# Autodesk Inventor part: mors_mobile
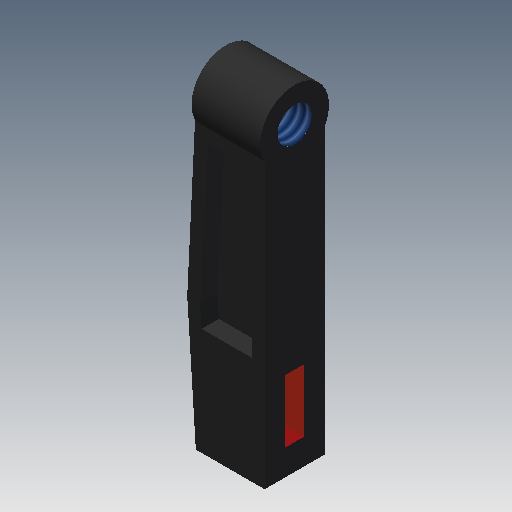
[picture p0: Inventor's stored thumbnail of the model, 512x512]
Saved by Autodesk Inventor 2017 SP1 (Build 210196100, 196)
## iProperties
Shininess: 64.0
Length Units: 11269
Angle Units: 11279
Time Units: 11290
Mass Units: 11283
Length Display Precision: 3
Angle Display Precision: 2
Compacted: True
Part Number: mors_mobile
Document SubType Name: Modeling
Created: 2003-07
Material: Générique
Designer: trameau
Density: 1 g/cm^3
Appearance: Caoutchouc (Noir)
Density: 0.0
Volumn: 0.0
Area: 0.0
PropertySet Name: Model Information
Control State: 0
Master: False
Checked Out: False
Author: trameau
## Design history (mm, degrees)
sketch "Esquisse1"
  geometry: L1 (17.214, 43.337)-(17.214, -26.663); L2 (17.214, -26.663)-(1.214, -26.663); L3 (1.214, -26.663)-(-0.786, 3.337); L4 (-0.786, 3.337)-(1.214, 43.337); L5 (1.214, 43.337)-(17.214, 43.337)
  constraints: 10 end point, 1 parallel, 1 perpendicular, 1 vertical
  dimensions: "d0" = 70 distance of L1.start L1.end; "d1" = 16 distance of L1.end L2.end; "d2" = 18 distance from line of L1 L3.end; "d3" = 16 distance of L4.end L1.start (= d1); "d4" = 30 distance from line of L2 L3.end
extrude "Extrusion1" new body sketch "Esquisse1" distance "d5" = 14; taper "d6" = 0 deg
sketch "Esquisse2"
  geometry: L1 (0, 0)-(-14, 0) reference; C1 r 8 at (-7, 70)
  constraints: 1 centre point
  dimensions: "d7" = 70 distance from line of L1 C1.centre; "d8" = 16 diameter of C1
extrude "Extrusion2" join sketch "Esquisse2" distance "d9" = 16; taper "d10" = 0 deg
sketch "Esquisse3"
  geometry: A1 r 8 centre (7, 70) between (14, 66.127) and (0, 66.127) reference
hole "Perçage1" sketch "Esquisse3" at (7, 70) diameter "d11" = 8; stored, may be unused: countersink angle "d15" = 82 deg, drill point angle "d17" = 118 deg; dims "d12" = 6, "d13" = 4, "d14" = 2, "d16" = 8
sketch "Esquisse4"
  geometry: L1 (14, 0)-(0, 0) reference; L2 (14, 66.127)-(14, 0) reference; L3 (4.75, 20.6)-(9.25, 20.6); L4 (9.25, 20.6)-(9.25, 6); L5 (9.25, 6)-(4.75, 6); L6 (4.75, 6)-(4.75, 20.6)
  constraints: 8 end point, 2 parallel, 1 horizontal, 1 perpendicular
  dimensions: "d18" = 4.5 distance of L4.end L5.end; "d19" = 14.6 distance of L3.end L4.end; "d20" = 4.75 distance between parallel lines of L2 L4; "d21" = 6 distance between parallel lines of L1 L5
sketch "Esquisse5"
  geometry: L1 (1.214, -26.663)-(-0.786, 3.337) reference; L2 (-0.786, 3.337)-(1.214, 39.464); L3 (4.053, 36.464)-(14.214, 36.464); L4 (14.214, -25.063)-(4.021, -25.063); L5 (2.22, 3.354)-(4.053, 36.464); L6 (17.214, -6.063)-(-0.159, -6.063) reference; L7 (14.214, -1.663)-(2.554, -1.663); L8 (-0.453, -1.663)-(-1.063, -1.663); L9 (4.021, -25.063)-(2.754, -6.063); L10 (2.554, -1.663)-(2.22, 3.354); L11 (14.214, 36.464)-(14.214, -1.663); L12 (14.214, -6.063)-(14.214, -25.063)
  constraints: 20 end point, 4 point on line, 2 parallel
  dimensions: "d24" = 3 distance between parallel lines of L2 L5
extrude "Extrusion4" cut sketch "Esquisse5" distance "d26" = 4; taper "d27" = 0 deg
node "Plan de construction1"
mirror "Symétrie1"
sketch "Esquisse6"
  geometry: L1 (0, -30.067)-(14, -30.067) reference; L2 (4.75, -10.067)-(9.25, -10.067); L3 (9.25, -10.067)-(9.25, -25.567); L4 (9.25, -25.567)-(4.75, -25.567); L5 (4.75, -25.567)-(4.75, -10.067)
  constraints: 8 end point, 2 parallel, 1 horizontal, 1 perpendicular
  dimensions: "d29" = 4.5 distance of L3.end L4.end (= d18); "d31" = 4.5 distance between parallel lines of L1 L4; "d32" = 15.5 distance of L4.end L2.start
feature "Lissage1" sketch "Esquisse6" dims "d33" = 0, "d34" = 90 deg, "d35" = 0, "d36" = 90 deg
node "Solide1"
node "Corps solides"
node "Corps surfaciques"
other parameters: "d25" = 3, "d28" = -7
